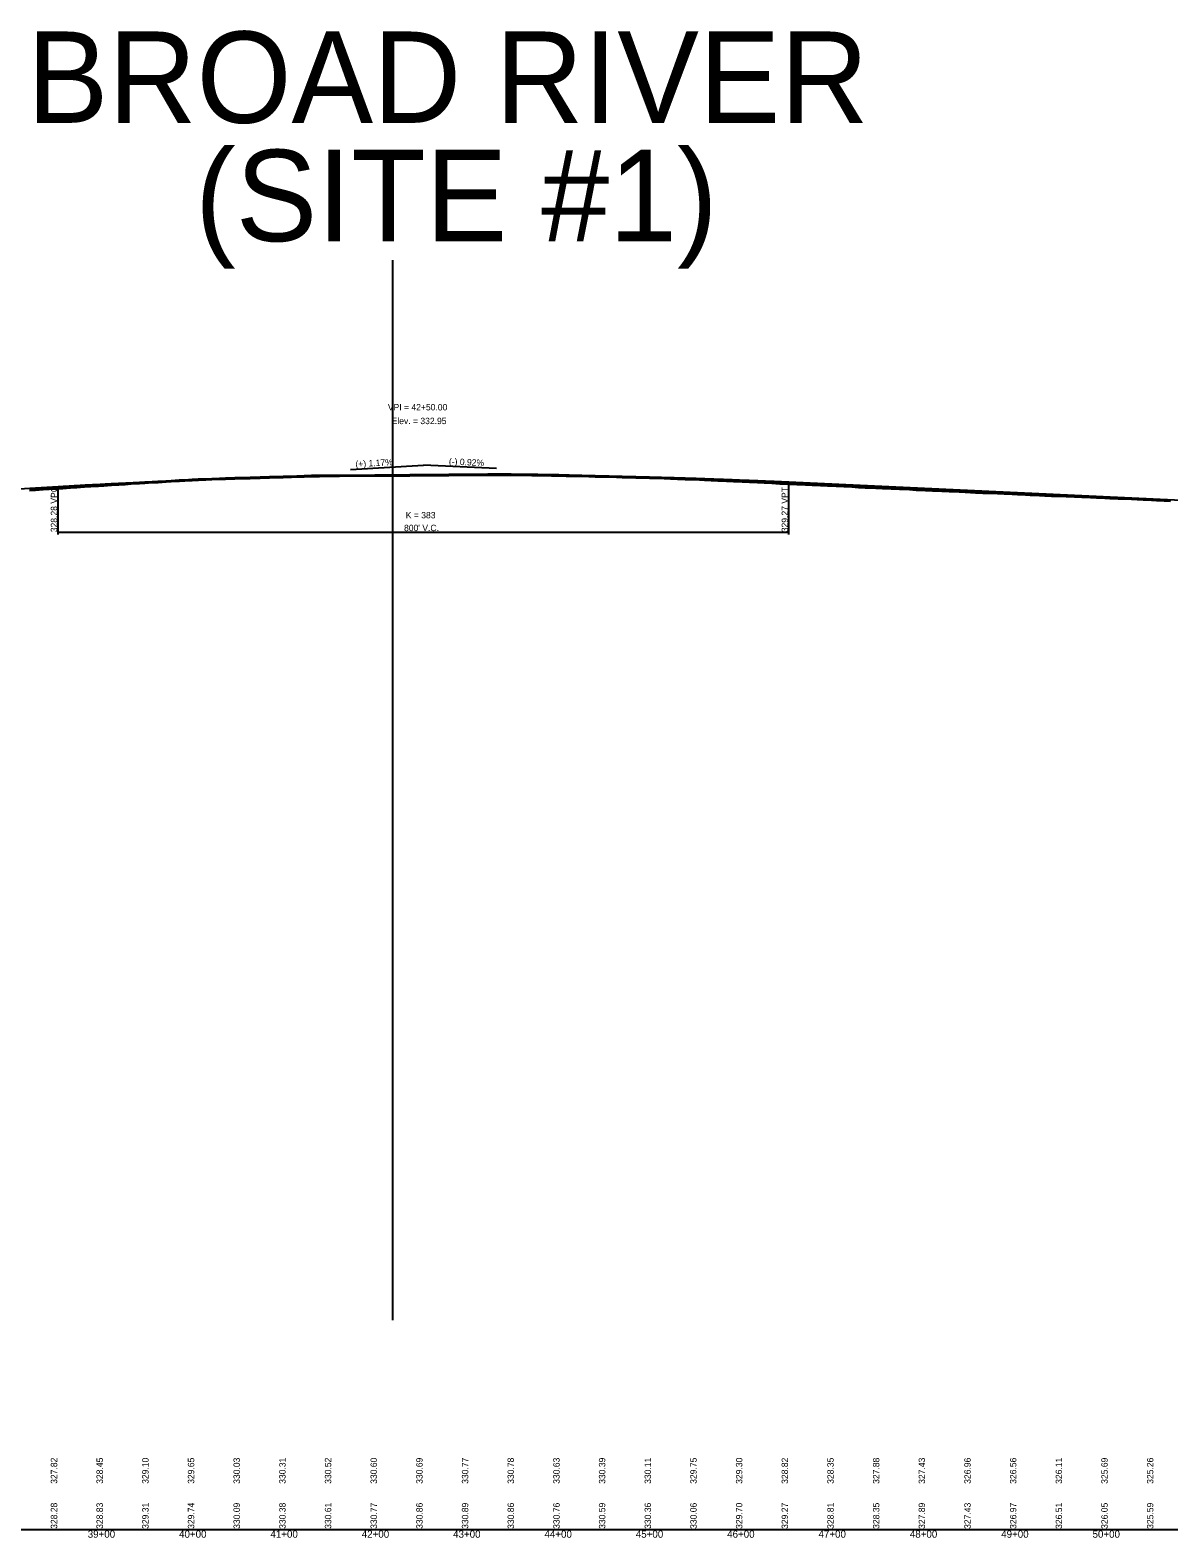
# Model space of a CAD drawing. Extents: x 1876258 to 1926563, y 729739 to 834437.
# Drawn here: x 1882182 to 1883429, y 830495 to 832145 of the extents above; entities that cross this region are included whole.
import ezdxf

# ---------------------------------------------------------------- set-up
doc = ezdxf.new("R2010")
doc.units = 0
for name, color, linetype in [('RD_EX_BldgApp', 7, 'Continuous'), ('RD_EX_H2O_BlueLn', 7, 'Continuous'), ('RD_EX_RailRoad', 7, 'Continuous'), ('RD_HC_Data', 7, 'Continuous'), ('RD_HC_Data_Tic', 7, 'Continuous'), ('RD_HC_TX_Sta50', 7, 'Continuous'), ('RD_PD_ALT3_CL', 7, 'Continuous'), ('RD_PD_ALT5_CL', 7, 'Continuous'), ('RD_PD_Final_Cl', 7, 'Continuous')]:
    doc.layers.add(name, color=color, linetype=linetype)

msp = doc.modelspace()

# ---------------------------------------------------------------- linework, layer by layer
at = {"layer": 'RD_EX_BldgApp'}
for points in [[(1882181.8, 831641.5), (1882188.3, 831641.9), (1882196.7, 831642.5), (1882203.3, 831642.8), (1882212, 831643.3), (1882218.3, 831643.7), (1882226.8, 831644.2), (1882233.5, 831644.6), (1882242.1, 831645.2), (1882248.8, 831645.6), (1882257.4, 831646.2), (1882263.3, 831646.6), (1882271.4, 831647.1), (1882277.4, 831647.4), (1882279.5, 831647.5), (1882286.5, 831648.1), (1882293.1, 831648.5), (1882302.3, 831649.1), (1882308, 831649.5), (1882316.3, 831650), (1882322.5, 831650.3), (1882331.2, 831650.7), (1882336.9, 831651.1), (1882345.8, 831651.6), (1882351.7, 831652), (1882360, 831652.4), (1882366.6, 831652.7), (1882374.9, 831653.1), (1882381.3, 831653.3)], [(1882381.3, 831653.3), (1882389.7, 831653.6), (1882396.2, 831653.9), (1882406.6, 831654.2), (1882412.8, 831654.4), (1882423.3, 831654.6), (1882428.6, 831654.8), (1882434.4, 831654.9), (1882444.5, 831655.3), (1882450.5, 831655.5), (1882459.5, 831655.7), (1882461.8, 831655.8), (1882463.6, 831655.9), (1882468.7, 831656), (1882474.7, 831656.2), (1882482.5, 831656.4), (1882489.2, 831656.6), (1882490.9, 831656.7), (1882499.3, 831656.8), (1882521.2, 831656.9), (1882598.1, 831657.6), (1882683.4, 831658.3), (1882685.3, 831658.3), (1882692.3, 831658.3), (1882694.2, 831658.3), (1882702.3, 831658.3), (1882709, 831658.2), (1882716, 831658.1), (1882723.5, 831658), (1882731.6, 831657.9), (1882738.1, 831657.8), (1882745.3, 831657.8), (1882753.2, 831657.6), (1882761.1, 831657.5), (1882769.2, 831657.2), (1882772.6, 831657.1), (1882780.1, 831657.1), (1882786.5, 831656.9), (1882794.1, 831656.7), (1882801.2, 831656.5), (1882809.2, 831656.3), (1882816.4, 831656.2), (1882824.5, 831655.9), (1882830.7, 831655.7), (1882839.1, 831655.5), (1882845.7, 831655.4), (1882853.8, 831655.1), (1882860.6, 831654.9), (1882869.6, 831654.7), (1882876.6, 831654.4), (1882883.4, 831654.2), (1882891.3, 831653.9), (1882899.6, 831653.5), (1882907.2, 831653.3), (1882915.1, 831653), (1882920.8, 831652.7), (1882925.6, 831652.5), (1882928, 831652.4), (1882935.2, 831652.1), (1882944.8, 831651.6), (1882952.4, 831651.3), (1882961.9, 831650.8), (1882970, 831650.4), (1882978.9, 831650.1), (1882986.1, 831649.7), (1882994.6, 831649.3), (1883003.2, 831648.8), (1883012.8, 831648.4), (1883021.7, 831647.9), (1883031.2, 831647.5), (1883038.6, 831647.2), (1883047.6, 831646.7), (1883055.5, 831646.3), (1883065, 831646), (1883073.2, 831645.6), (1883082.1, 831645.2), (1883089.3, 831644.8), (1883096.6, 831644.4), (1883102.6, 831644.2), (1883108.3, 831643.9), (1883115.6, 831643.6), (1883125.2, 831643.2), (1883134.1, 831642.7), (1883145.2, 831642.3), (1883152.5, 831641.9), (1883162.7, 831641.5), (1883170.2, 831641.1), (1883180.6, 831640.6), (1883188.5, 831640.3), (1883199.4, 831639.8), (1883205.9, 831639.5), (1883217.3, 831638.9), (1883225.3, 831638.6), (1883231.4, 831638.3), (1883241.3, 831638), (1883248.7, 831637.7), (1883257.6, 831637.3), (1883263.5, 831637.1), (1883272.1, 831636.7), (1883274.8, 831636.6), (1883277.3, 831636.4)], [(1883277.3, 831636.4), (1883281.6, 831636.2), (1883293.2, 831635.7), (1883300.7, 831635.3), (1883309.7, 831635), (1883316.7, 831634.7), (1883325.9, 831634.3), (1883333.7, 831634), (1883343.2, 831633.6), (1883350, 831633.3), (1883359, 831632.9), (1883364.4, 831632.7), (1883373.7, 831632.3), (1883378.7, 831632.1), (1883388.3, 831631.7), (1883394.4, 831631.5), (1883401.1, 831631.2), (1883410.1, 831630.7), (1883415.4, 831630.5), (1883424, 831630.1), (1883431, 831629.8)]]:
    msp.add_lwpolyline(points, dxfattribs=at)
at = {"layer": 'RD_EX_H2O_BlueLn'}
for p, q in [((1882213.1, 831593.2), (1882213.1, 831645.7)), ((1883013.1, 831593.2), (1883013.1, 831650.7)), ((1882213.1, 831595.7), (1883013.1, 831595.7))]:
    msp.add_line(p, q, dxfattribs=at)
at = {"layer": 'RD_HC_Data_Tic'}
msp.add_line((1882579.5, 830733.3), (1882579.5, 831893.4), dxfattribs=at)
msp.add_lwpolyline([(1882181.8, 831642.8), (1882188.2, 831643.2), (1882196.6, 831643.7), (1882203.2, 831644.1), (1882211.9, 831644.6), (1882218.2, 831645), (1882226.7, 831645.5), (1882233.5, 831645.9), (1882242, 831646.4), (1882248.7, 831646.8), (1882257.3, 831647.4), (1882263.2, 831647.8), (1882271.3, 831648.3), (1882277.4, 831648.7), (1882279.4, 831648.8), (1882286.4, 831649.3), (1882293, 831649.7), (1882302.2, 831650.4), (1882307.9, 831650.7), (1882316.2, 831651.2), (1882322.4, 831651.5), (1882331.1, 831652), (1882336.8, 831652.3), (1882345.7, 831652.9), (1882351.6, 831653.2), (1882359.9, 831653.6), (1882366.5, 831654), (1882374.9, 831654.3), (1882381.2, 831654.6), (1882389.6, 831654.9), (1882396.2, 831655.1), (1882406.5, 831655.5), (1882412.8, 831655.7), (1882423.3, 831655.8), (1882428.5, 831656), (1882434.4, 831656.2), (1882444.4, 831656.6), (1882450.5, 831656.7), (1882459.4, 831657), (1882461.8, 831657.1), (1882463.5, 831657.1), (1882468.6, 831657.2), (1882474.6, 831657.4), (1882482.5, 831657.7), (1882489.1, 831657.9), (1882490.9, 831658), (1882499.3, 831658), (1882521.2, 831658.2), (1882598.1, 831658.9), (1882683.4, 831659.5), (1882685.2, 831659.6), (1882692.2, 831659.6), (1882694.2, 831659.6), (1882702.3, 831659.5), (1882709, 831659.5), (1882716, 831659.4), (1882723.5, 831659.3), (1882731.6, 831659.2), (1882738.1, 831659.1), (1882745.3, 831659), (1882753.3, 831658.9), (1882761.1, 831658.7), (1882769.2, 831658.5), (1882772.6, 831658.4), (1882780.1, 831658.3), (1882786.6, 831658.2), (1882794.1, 831657.9), (1882801.2, 831657.8), (1882809.2, 831657.6), (1882816.5, 831657.4), (1882824.5, 831657.1), (1882830.7, 831657), (1882839.1, 831656.8), (1882845.7, 831656.6), (1882853.8, 831656.3), (1882860.6, 831656.2), (1882869.7, 831655.9), (1882876.6, 831655.7), (1882883.5, 831655.4), (1882891.4, 831655.1), (1882899.7, 831654.8), (1882907.3, 831654.6), (1882915.2, 831654.2), (1882920.9, 831653.9), (1882925.6, 831653.8), (1882928.1, 831653.7), (1882935.3, 831653.3), (1882944.8, 831652.8), (1882952.5, 831652.5), (1882961.9, 831652.1), (1882970.1, 831651.7), (1882978.9, 831651.3), (1882986.1, 831650.9), (1882994.6, 831650.6), (1883003.2, 831650.1), (1883012.9, 831649.7), (1883021.8, 831649.2), (1883031.2, 831648.8), (1883038.6, 831648.4), (1883047.7, 831647.9), (1883055.5, 831647.6), (1883065, 831647.2), (1883073.3, 831646.8), (1883082.2, 831646.4), (1883089.4, 831646), (1883096.6, 831645.7), (1883102.7, 831645.4), (1883108.3, 831645.2), (1883115.7, 831644.8), (1883125.2, 831644.4), (1883134.2, 831644), (1883145.2, 831643.5), (1883152.6, 831643.2), (1883162.8, 831642.7), (1883170.3, 831642.4), (1883180.6, 831641.9), (1883188.6, 831641.5), (1883199.4, 831641), (1883205.9, 831640.7), (1883217.3, 831640.1), (1883225.3, 831639.8), (1883231.5, 831639.6), (1883241.3, 831639.2), (1883248.8, 831638.9), (1883257.6, 831638.6), (1883263.6, 831638.3), (1883272.2, 831638), (1883274.8, 831637.8), (1883277.4, 831637.6), (1883281.7, 831637.4), (1883293.3, 831636.9), (1883300.7, 831636.5), (1883309.8, 831636.2), (1883316.7, 831635.9), (1883325.9, 831635.6), (1883333.8, 831635.3), (1883343.3, 831634.9), (1883350.1, 831634.6), (1883359, 831634.2), (1883364.5, 831633.9), (1883373.7, 831633.6), (1883378.7, 831633.3), (1883388.3, 831632.9), (1883394.4, 831632.7), (1883401.2, 831632.4), (1883410.2, 831632), (1883415.5, 831631.7), (1883424.1, 831631.4), (1883431.1, 831631)], dxfattribs=at)
at = {"layer": 'RD_HC_TX_Sta50'}
for p in [(1882533.2, 831664.4), (1882693, 831665.4)]:
    msp.add_line(p, (1882613.1, 831669), dxfattribs=at)
at = {"layer": 'RD_PD_ALT5_CL'}
for p, q in [((1881043.1, 831577.3), (1882213.1, 831645.7)), ((1883013.1, 831650.7), (1883743.1, 831617.1))]:
    msp.add_line(p, q, dxfattribs=at)
msp.add_spline([(1882213.1, 831645.7), (1882229.1, 831646.6), (1882245.1, 831647.5), (1882261.1, 831648.3), (1882277.1, 831649.2), (1882293.1, 831649.9), (1882309.1, 831650.7), (1882325.1, 831651.4), (1882341.1, 831652.1), (1882357.1, 831652.7), (1882373.1, 831653.4), (1882389.1, 831653.9), (1882405.1, 831654.5), (1882421.1, 831655), (1882437.1, 831655.5), (1882453.1, 831655.9), (1882469.1, 831656.4), (1882485.1, 831656.7), (1882501.1, 831657.1), (1882517.1, 831657.4), (1882533.1, 831657.7), (1882549.1, 831657.9), (1882565.1, 831658.2), (1882581.1, 831658.3), (1882597.1, 831658.5), (1882613.1, 831658.6), (1882629.1, 831658.7), (1882645.1, 831658.7), (1882661.1, 831658.8), (1882677.1, 831658.7), (1882693.1, 831658.7), (1882709.1, 831658.6), (1882725.1, 831658.5), (1882741.1, 831658.3), (1882757.1, 831658.1), (1882773.1, 831657.9), (1882789.1, 831657.7), (1882805.1, 831657.4), (1882821.1, 831657.1), (1882837.1, 831656.7), (1882853.1, 831656.3), (1882869.1, 831655.9), (1882885.1, 831655.5), (1882901.1, 831655), (1882917.1, 831654.5), (1882933.1, 831653.9), (1882949.1, 831653.3), (1882965.1, 831652.7), (1882981.1, 831652.1), (1882997.1, 831651.4), (1883013.1, 831650.7)], degree=3, dxfattribs=at)
at = {"layer": 'RD_PD_Final_Cl'}
msp.add_line((1878363.1, 830504.3), (1926563.1, 830504.3), dxfattribs=at)

# ---------------------------------------------------------------- texts
at = {"layer": 'RD_EX_H2O_BlueLn'}
for s, p in [("800' V.C.", (1882591.8, 831596.9)), ('K = 383', (1882593.7, 831610.9))]:
    msp.add_text(s, height=7, dxfattribs=at).set_placement(p)
at = {"layer": 'RD_EX_RailRoad'}
for s, p in [('328.28 VPC', (1882212.1, 831595.7)), ('329.27 VPT', (1883012.1, 831595.7)), ('327.82', (1882212.1, 830554.3)), ('328.45', (1882262.1, 830554.3)), ('329.10', (1882312.1, 830554.3)), ('329.65', (1882362.1, 830554.3)), ('330.03', (1882412.1, 830554.3)), ('330.31', (1882462.1, 830554.3)), ('330.52', (1882512.1, 830554.3)), ('330.60', (1882562.1, 830554.3)), ('330.69', (1882612.1, 830554.3)), ('330.77', (1882662.1, 830554.3)), ('330.78', (1882712.1, 830554.3)), ('330.63', (1882762.1, 830554.3)), ('330.39', (1882812.1, 830554.3)), ('330.11', (1882862.1, 830554.3)), ('329.75', (1882912.1, 830554.3)), ('329.30', (1882962.1, 830554.3)), ('328.82', (1883012.1, 830554.3)), ('328.35', (1883062.1, 830554.3)), ('327.88', (1883112.1, 830554.3)), ('327.43', (1883162.1, 830554.3)), ('326.96', (1883212.1, 830554.3)), ('326.56', (1883262.1, 830554.3)), ('326.11', (1883312.1, 830554.3)), ('325.69', (1883362.1, 830554.3)), ('325.26', (1883412.1, 830554.3)), ('328.28', (1882212.1, 830505)), ('328.83', (1882262.1, 830505)), ('329.31', (1882312.1, 830505)), ('329.74', (1882362.1, 830505)), ('330.09', (1882412.1, 830505)), ('330.38', (1882462.1, 830505)), ('330.61', (1882512.1, 830505)), ('330.77', (1882562.1, 830505)), ('330.86', (1882612.1, 830505)), ('330.89', (1882662.1, 830505)), ('330.86', (1882712.1, 830505)), ('330.76', (1882762.1, 830505)), ('330.59', (1882812.1, 830505)), ('330.36', (1882862.1, 830505)), ('330.06', (1882912.1, 830505)), ('329.70', (1882962.1, 830505)), ('329.27', (1883012.1, 830505)), ('328.81', (1883062.1, 830505)), ('328.35', (1883112.1, 830505)), ('327.89', (1883162.1, 830505)), ('327.43', (1883212.1, 830505)), ('326.97', (1883262.1, 830505)), ('326.51', (1883312.1, 830505)), ('326.05', (1883362.1, 830505)), ('325.59', (1883412.1, 830505))]:
    msp.add_text(s, height=7, rotation=90, dxfattribs=at).set_placement(p)
at = {"layer": 'RD_HC_Data'}
for s, p in [('VPI = 42+50.00', (1882574.1, 831729)), ('Elev. = 332.95', (1882578.2, 831714))]:
    msp.add_text(s, height=7, dxfattribs=at).set_placement(p)
at = {"layer": 'RD_HC_Data_Tic'}
for s, p in [('BROAD RIVER', (1882178.9, 832043.7)), ('(SITE #1)', (1882363, 831914.2))]:
    msp.add_text(s, height=100, dxfattribs=at).set_placement(p)
at = {"layer": 'RD_HC_TX_Sta50'}
for s, rotation, p in [('(+) 1.17%', 3.3433, (1882538.8, 831666.7)), ('(-) 0.92%', 357.3675, (1882640.8, 831669.8))]:
    msp.add_text(s, height=7, rotation=rotation, dxfattribs=at).set_placement(p)
at = {"layer": 'RD_PD_ALT3_CL'}
for s, p in [('39+00', (1882245.5, 830495.3)), ('39+00', (1882245.5, 830495.3)), ('40+00', (1882345.5, 830495.3)), ('40+00', (1882345.5, 830495.3)), ('41+00', (1882445.5, 830495.3)), ('41+00', (1882445.5, 830495.3)), ('42+00', (1882545.5, 830495.3)), ('42+00', (1882545.5, 830495.3)), ('43+00', (1882645.5, 830495.3)), ('43+00', (1882645.5, 830495.3)), ('44+00', (1882745.5, 830495.3)), ('44+00', (1882745.5, 830495.3)), ('45+00', (1882845.5, 830495.3)), ('45+00', (1882845.5, 830495.3)), ('46+00', (1882945.5, 830495.3)), ('46+00', (1882945.5, 830495.3)), ('47+00', (1883045.5, 830495.3)), ('47+00', (1883045.5, 830495.3)), ('48+00', (1883145.5, 830495.3)), ('48+00', (1883145.5, 830495.3)), ('49+00', (1883245.5, 830495.3)), ('49+00', (1883245.5, 830495.3)), ('50+00', (1883345.5, 830495.3)), ('50+00', (1883345.5, 830495.3))]:
    msp.add_text(s, height=8, dxfattribs=at).set_placement(p)

doc.saveas('drawing.dxf')
